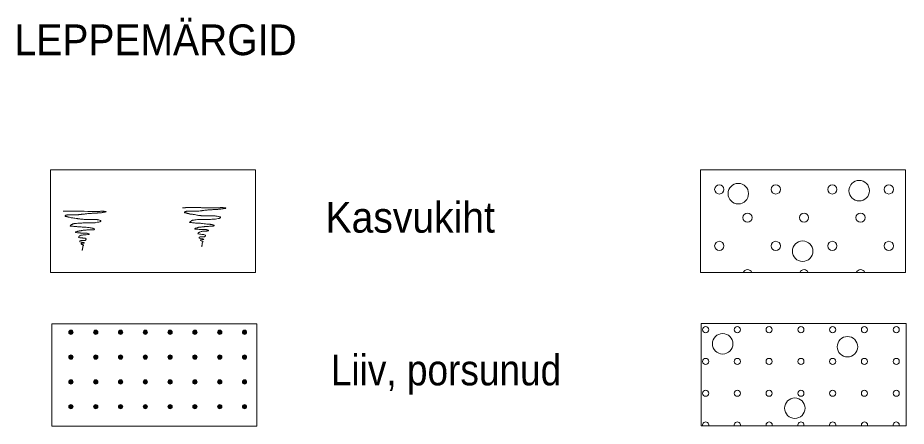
# Model space of a CAD drawing. Extents: x 640104 to 640970, y 6442278 to 6442689.
# Drawn here: x 640605.1 to 640691.8, y 6442439 to 6442478.8 of the extents above; entities that cross this region are included whole.
import ezdxf
from ezdxf.enums import TextEntityAlignment as Align

# ---------------------------------------------------------------- set-up
doc = ezdxf.new("R2010")
doc.units = 0
doc.header["$LTSCALE"] = 1.2
doc.layers.add('50', color=7, linetype='Continuous', lineweight=13)

msp = doc.modelspace()

# ---------------------------------------------------------------- hatches: boundary and pattern name
at = {"layer": '50'}
for points in [[(640610.534, 6442448.158, 1), (640610.114, 6442448.158, 1)], [(640612.954, 6442448.158, 1), (640612.534, 6442448.158, 1)], [(640615.374, 6442448.158, 1), (640614.954, 6442448.158, 1)], [(640617.794, 6442448.158, 1), (640617.374, 6442448.158, 1)], [(640620.214, 6442448.158, 1), (640619.794, 6442448.158, 1)], [(640622.634, 6442448.158, 1), (640622.214, 6442448.158, 1)], [(640625.054, 6442448.158, 1), (640624.634, 6442448.158, 1)], [(640627.474, 6442448.158, 1), (640627.054, 6442448.158, 1)], [(640610.534, 6442445.738, 1), (640610.114, 6442445.738, 1)], [(640612.954, 6442445.738, 1), (640612.534, 6442445.738, 1)], [(640615.374, 6442445.738, 1), (640614.954, 6442445.738, 1)], [(640617.794, 6442445.738, 1), (640617.374, 6442445.738, 1)], [(640620.214, 6442445.738, 1), (640619.794, 6442445.738, 1)], [(640622.634, 6442445.738, 1), (640622.214, 6442445.738, 1)], [(640625.054, 6442445.738, 1), (640624.634, 6442445.738, 1)], [(640627.474, 6442445.738, 1), (640627.054, 6442445.738, 1)], [(640610.534, 6442443.318, 1), (640610.114, 6442443.318, 1)], [(640612.954, 6442443.318, 1), (640612.534, 6442443.318, 1)], [(640615.374, 6442443.318, 1), (640614.954, 6442443.318, 1)], [(640617.794, 6442443.318, 1), (640617.374, 6442443.318, 1)], [(640620.214, 6442443.318, 1), (640619.794, 6442443.318, 1)], [(640622.634, 6442443.318, 1), (640622.214, 6442443.318, 1)], [(640625.054, 6442443.318, 1), (640624.634, 6442443.318, 1)], [(640627.474, 6442443.318, 1), (640627.054, 6442443.318, 1)], [(640610.534, 6442440.898, 1), (640610.114, 6442440.898, 1)], [(640612.954, 6442440.898, 1), (640612.534, 6442440.898, 1)], [(640615.374, 6442440.898, 1), (640614.954, 6442440.898, 1)], [(640617.794, 6442440.898, 1), (640617.374, 6442440.898, 1)], [(640620.214, 6442440.898, 1), (640619.794, 6442440.898, 1)], [(640622.634, 6442440.898, 1), (640622.214, 6442440.898, 1)], [(640625.054, 6442440.898, 1), (640624.634, 6442440.898, 1)], [(640627.474, 6442440.898, 1), (640627.054, 6442440.898, 1)]]:
    msp.add_hatch(color=256, dxfattribs=at).paths.add_polyline_path(points)

# ---------------------------------------------------------------- linework, layer by layer
for points in [[(640608.34, 6442464), (640628.34, 6442464), (640628.34, 6442454), (640608.34, 6442454)], [(640671.77, 6442464), (640691.77, 6442464), (640691.77, 6442454), (640671.77, 6442454)], [(640608.47, 6442448.99), (640628.47, 6442448.99), (640628.47, 6442438.99), (640608.47, 6442438.99)], [(640671.84, 6442449.03), (640691.84, 6442449.03), (640691.84, 6442439.03), (640671.84, 6442439.03)]]:
    msp.add_lwpolyline(points, close=True, dxfattribs=at)
for points in [[(640621.22, 6442460.31), (640621.28, 6442460.31), (640621.38, 6442460.31), (640621.49, 6442460.31), (640621.52, 6442460.33), (640621.62, 6442460.33), (640621.78, 6442460.33), (640622.1, 6442460.33), (640622.28, 6442460.33), (640622.32, 6442460.33), (640622.36, 6442460.33), (640622.43, 6442460.33), (640622.51, 6442460.33), (640622.62, 6442460.33), (640622.7, 6442460.33), (640622.76, 6442460.33), (640622.85, 6442460.33), (640622.92, 6442460.33), (640622.99, 6442460.33), (640623.08, 6442460.31), (640623.12, 6442460.31), (640623.2, 6442460.31), (640623.29, 6442460.31), (640623.63, 6442460.3), (640623.94, 6442460.29), (640624.04, 6442460.29), (640624.1, 6442460.29), (640624.13, 6442460.29), (640624.18, 6442460.29), (640624.25, 6442460.29), (640624.35, 6442460.3), (640624.4, 6442460.3), (640624.43, 6442460.3), (640624.46, 6442460.3), (640624.49, 6442460.3), (640624.56, 6442460.29), (640624.6, 6442460.29), (640624.65, 6442460.29), (640624.74, 6442460.3), (640624.8, 6442460.3), (640624.88, 6442460.31), (640624.91, 6442460.33), (640624.98, 6442460.33), (640625.02, 6442460.34), (640625.07, 6442460.34), (640625.12, 6442460.34), (640625.15, 6442460.33), (640625.19, 6442460.31), (640625.24, 6442460.3), (640625.27, 6442460.3)], [(640625.27, 6442460.3), (640625.32, 6442460.29), (640625.36, 6442460.29), (640625.4, 6442460.29), (640625.43, 6442460.27), (640625.4, 6442460.25), (640625.42, 6442460.27), (640625.38, 6442460.25), (640625.33, 6442460.24), (640625.27, 6442460.23), (640625.24, 6442460.23), (640625.19, 6442460.23), (640625.15, 6442460.22), (640625.12, 6442460.22), (640625.09, 6442460.19), (640625.03, 6442460.19), (640624.96, 6442460.18), (640624.92, 6442460.18), (640624.8, 6442460.17), (640624.76, 6442460.16), (640624.72, 6442460.16), (640624.67, 6442460.15), (640624.62, 6442460.15), (640624.59, 6442460.15), (640624.53, 6442460.13), (640624.49, 6442460.13), (640624.38, 6442460.13), (640624.32, 6442460.13), (640624.25, 6442460.13), (640624.17, 6442460.13), (640624.11, 6442460.12), (640624.06, 6442460.12), (640624, 6442460.11), (640623.94, 6442460.11), (640623.77, 6442460.11), (640623.74, 6442460.11), (640623.7, 6442460.1), (640623.63, 6442460.09), (640623.53, 6442460.07), (640623.45, 6442460.06), (640623.39, 6442460.06), (640623.3, 6442460.05), (640623.24, 6442460.05), (640623.2, 6442460.03), (640623.14, 6442460.03), (640623.11, 6442460.01), (640623.08, 6442460.01), (640623.02, 6442460.01), (640622.97, 6442460), (640622.93, 6442460), (640622.8, 6442459.99), (640622.75, 6442459.99)], [(640609.56, 6442459.97), (640609.62, 6442459.97), (640609.72, 6442459.97), (640609.83, 6442459.97), (640609.86, 6442459.98), (640609.96, 6442459.98), (640610.12, 6442459.98), (640610.44, 6442459.98), (640610.62, 6442459.98), (640610.66, 6442459.98), (640610.7, 6442459.98), (640610.77, 6442459.98), (640610.85, 6442459.98), (640610.96, 6442459.98), (640611.04, 6442459.98), (640611.1, 6442459.98), (640611.19, 6442459.98), (640611.26, 6442459.98), (640611.33, 6442459.98), (640611.42, 6442459.97), (640611.46, 6442459.97), (640611.54, 6442459.97), (640611.63, 6442459.97), (640611.97, 6442459.95), (640612.28, 6442459.94), (640612.38, 6442459.94), (640612.44, 6442459.94), (640612.47, 6442459.94), (640612.52, 6442459.94), (640612.59, 6442459.94), (640612.69, 6442459.95), (640612.74, 6442459.95), (640612.77, 6442459.95), (640612.8, 6442459.95), (640612.83, 6442459.95), (640612.9, 6442459.94), (640612.94, 6442459.94), (640612.99, 6442459.94), (640613.08, 6442459.95), (640613.14, 6442459.95), (640613.22, 6442459.97), (640613.25, 6442459.98), (640613.32, 6442459.98), (640613.36, 6442459.99), (640613.41, 6442459.99), (640613.46, 6442459.99), (640613.49, 6442459.98), (640613.53, 6442459.97), (640613.58, 6442459.95), (640613.61, 6442459.95)], [(640611.09, 6442459.64), (640611.06, 6442459.63), (640611, 6442459.63), (640610.96, 6442459.62), (640610.92, 6442459.62), (640610.89, 6442459.62), (640610.84, 6442459.62), (640610.79, 6442459.62), (640610.74, 6442459.62), (640610.67, 6442459.62), (640610.64, 6442459.62), (640610.58, 6442459.63), (640610.54, 6442459.63), (640610.5, 6442459.63), (640610.47, 6442459.63), (640610.42, 6442459.63), (640610.37, 6442459.63), (640610.3, 6442459.63), (640610.26, 6442459.63), (640610.23, 6442459.63), (640610.17, 6442459.63), (640610.13, 6442459.63), (640610.08, 6442459.63), (640610.05, 6442459.63), (640610, 6442459.63), (640609.95, 6442459.62), (640609.92, 6442459.59), (640609.87, 6442459.59), (640609.83, 6442459.58), (640609.81, 6442459.57), (640609.78, 6442459.56), (640609.76, 6442459.53), (640609.75, 6442459.5), (640609.76, 6442459.46), (640609.86, 6442459.45), (640609.92, 6442459.45), (640609.95, 6442459.43), (640610, 6442459.43), (640610.04, 6442459.41), (640610.06, 6442459.4), (640610.12, 6442459.4), (640610.17, 6442459.39), (640610.2, 6442459.38), (640610.28, 6442459.35), (640610.35, 6442459.34), (640610.42, 6442459.34), (640610.47, 6442459.33), (640610.52, 6442459.32), (640610.6, 6442459.31), (640610.71, 6442459.29)], [(640610.71, 6442459.29), (640610.85, 6442459.27), (640610.95, 6442459.25), (640611.01, 6442459.23), (640611.1, 6442459.22), (640611.2, 6442459.22), (640611.27, 6442459.21), (640611.33, 6442459.21), (640611.38, 6442459.19), (640611.46, 6442459.19), (640611.52, 6442459.19), (640611.61, 6442459.17), (640611.69, 6442459.17), (640611.76, 6442459.17), (640611.86, 6442459.17), (640611.94, 6442459.16), (640612, 6442459.16), (640612.04, 6442459.16), (640612.11, 6442459.16), (640612.18, 6442459.16), (640612.27, 6442459.16), (640612.36, 6442459.16), (640612.45, 6442459.16), (640612.51, 6442459.16), (640612.59, 6442459.16), (640612.63, 6442459.16), (640612.69, 6442459.16), (640612.75, 6442459.16), (640612.81, 6442459.15), (640612.87, 6442459.15), (640612.92, 6442459.14), (640613.05, 6442459.13), (640613.11, 6442459.1), (640613.17, 6442459.08), (640613.22, 6442459.07), (640613.25, 6442459.05), (640613.25, 6442459.02), (640613.24, 6442458.98), (640613.22, 6442458.97), (640613.19, 6442458.96), (640613.17, 6442458.93), (640613.12, 6442458.92), (640613.04, 6442458.9), (640612.89, 6442458.89), (640612.76, 6442458.86), (640612.69, 6442458.85), (640612.59, 6442458.85), (640612.51, 6442458.84), (640612.41, 6442458.84), (640612.28, 6442458.83), (640612.09, 6442458.83), (640611.92, 6442458.83)], [(640613.61, 6442459.95), (640613.66, 6442459.94), (640613.7, 6442459.94), (640613.74, 6442459.94), (640613.77, 6442459.92), (640613.74, 6442459.91), (640613.76, 6442459.92), (640613.72, 6442459.91), (640613.67, 6442459.89), (640613.61, 6442459.88), (640613.58, 6442459.88), (640613.53, 6442459.88), (640613.49, 6442459.87), (640613.46, 6442459.87), (640613.43, 6442459.85), (640613.37, 6442459.85), (640613.3, 6442459.83), (640613.26, 6442459.83), (640613.14, 6442459.82), (640613.1, 6442459.81), (640613.06, 6442459.81), (640613.01, 6442459.8), (640612.96, 6442459.8), (640612.93, 6442459.8), (640612.87, 6442459.79), (640612.83, 6442459.79), (640612.72, 6442459.79), (640612.66, 6442459.79), (640612.59, 6442459.79), (640612.51, 6442459.79), (640612.45, 6442459.77), (640612.4, 6442459.77), (640612.34, 6442459.76), (640612.28, 6442459.76), (640612.11, 6442459.76), (640612.08, 6442459.76), (640612.04, 6442459.75), (640611.97, 6442459.74), (640611.87, 6442459.73), (640611.79, 6442459.71), (640611.73, 6442459.71), (640611.64, 6442459.7), (640611.58, 6442459.7), (640611.54, 6442459.68), (640611.48, 6442459.68), (640611.45, 6442459.67), (640611.42, 6442459.67), (640611.36, 6442459.67), (640611.31, 6442459.65), (640611.27, 6442459.65), (640611.14, 6442459.64), (640611.09, 6442459.64)], [(640622.75, 6442459.99), (640622.72, 6442459.98), (640622.66, 6442459.98), (640622.62, 6442459.97), (640622.58, 6442459.97), (640622.55, 6442459.97), (640622.5, 6442459.97), (640622.45, 6442459.97), (640622.4, 6442459.97), (640622.33, 6442459.97), (640622.3, 6442459.97), (640622.24, 6442459.98), (640622.2, 6442459.98), (640622.16, 6442459.98), (640622.13, 6442459.98), (640622.08, 6442459.98), (640622.03, 6442459.98), (640621.96, 6442459.98), (640621.92, 6442459.98), (640621.89, 6442459.98), (640621.83, 6442459.98), (640621.79, 6442459.98), (640621.74, 6442459.98), (640621.71, 6442459.98), (640621.66, 6442459.98), (640621.61, 6442459.97), (640621.58, 6442459.94), (640621.53, 6442459.94), (640621.49, 6442459.93), (640621.47, 6442459.92), (640621.44, 6442459.91), (640621.42, 6442459.88), (640621.41, 6442459.85), (640621.42, 6442459.81), (640621.52, 6442459.8), (640621.58, 6442459.8), (640621.61, 6442459.77), (640621.66, 6442459.77), (640621.7, 6442459.76), (640621.72, 6442459.75), (640621.78, 6442459.75), (640621.83, 6442459.74), (640621.86, 6442459.73), (640621.94, 6442459.7), (640622.01, 6442459.69), (640622.08, 6442459.69), (640622.13, 6442459.68), (640622.18, 6442459.67), (640622.26, 6442459.65), (640622.37, 6442459.64)], [(640622.37, 6442459.64), (640622.51, 6442459.62), (640622.61, 6442459.59), (640622.67, 6442459.58), (640622.76, 6442459.57), (640622.86, 6442459.57), (640622.93, 6442459.56), (640622.99, 6442459.56), (640623.04, 6442459.53), (640623.12, 6442459.53), (640623.18, 6442459.53), (640623.27, 6442459.52), (640623.35, 6442459.52), (640623.42, 6442459.52), (640623.52, 6442459.52), (640623.6, 6442459.51), (640623.66, 6442459.51), (640623.7, 6442459.51), (640623.77, 6442459.51), (640623.84, 6442459.51), (640623.93, 6442459.51), (640624.02, 6442459.51), (640624.11, 6442459.51), (640624.17, 6442459.51), (640624.25, 6442459.51), (640624.29, 6442459.51), (640624.35, 6442459.51), (640624.41, 6442459.51), (640624.47, 6442459.5), (640624.53, 6442459.5), (640624.58, 6442459.49), (640624.71, 6442459.47), (640624.77, 6442459.45), (640624.83, 6442459.43), (640624.88, 6442459.41), (640624.91, 6442459.4), (640624.91, 6442459.37), (640624.9, 6442459.33), (640624.88, 6442459.32), (640624.85, 6442459.31), (640624.83, 6442459.28), (640624.78, 6442459.27), (640624.7, 6442459.25), (640624.55, 6442459.23), (640624.42, 6442459.21), (640624.35, 6442459.2), (640624.25, 6442459.2), (640624.17, 6442459.19), (640624.07, 6442459.19), (640623.94, 6442459.17), (640623.75, 6442459.17), (640623.58, 6442459.17)], [(640611.92, 6442458.83), (640611.84, 6442458.83), (640611.76, 6442458.83), (640611.68, 6442458.83), (640611.62, 6442458.83), (640611.56, 6442458.83), (640611.48, 6442458.83), (640611.39, 6442458.81), (640611.21, 6442458.81), (640611.13, 6442458.81), (640611.08, 6442458.8), (640611, 6442458.8), (640610.88, 6442458.78), (640610.74, 6442458.78), (640610.7, 6442458.77), (640610.64, 6442458.77), (640610.61, 6442458.75), (640610.58, 6442458.74), (640610.54, 6442458.74), (640610.5, 6442458.73), (640610.47, 6442458.72), (640610.44, 6442458.69), (640610.38, 6442458.66), (640610.35, 6442458.63), (640610.34, 6442458.61), (640610.3, 6442458.6), (640610.29, 6442458.57), (640610.26, 6442458.55), (640610.25, 6442458.53), (640610.28, 6442458.51), (640610.31, 6442458.51), (640610.37, 6442458.51), (640610.42, 6442458.51), (640610.53, 6442458.5), (640610.61, 6442458.49), (640610.71, 6442458.48), (640610.83, 6442458.47), (640610.89, 6442458.47), (640610.95, 6442458.44), (640611.01, 6442458.44), (640611.18, 6442458.44), (640611.31, 6442458.44), (640611.42, 6442458.43), (640611.52, 6442458.42), (640611.67, 6442458.41), (640611.81, 6442458.41), (640611.93, 6442458.37), (640612.02, 6442458.37), (640612.11, 6442458.37), (640612.2, 6442458.36)], [(640612.2, 6442458.36), (640612.24, 6442458.36), (640612.29, 6442458.35), (640612.38, 6442458.32), (640612.45, 6442458.31), (640612.5, 6442458.29), (640612.54, 6442458.27), (640612.6, 6442458.26), (640612.63, 6442458.25), (640612.64, 6442458.2), (640612.62, 6442458.19), (640612.59, 6442458.18), (640612.56, 6442458.17), (640612.44, 6442458.15), (640612.38, 6442458.15), (640612.34, 6442458.15), (640612.27, 6442458.15), (640612.18, 6442458.15), (640612.1, 6442458.14), (640612.05, 6442458.14), (640612, 6442458.14), (640611.87, 6442458.14), (640611.8, 6442458.12), (640611.76, 6442458.12), (640611.7, 6442458.12), (640611.67, 6442458.11), (640611.61, 6442458.11), (640611.52, 6442458.11), (640611.45, 6442458.09), (640611.37, 6442458.08), (640611.31, 6442458.07), (640611.27, 6442458.07), (640611.22, 6442458.07), (640611.19, 6442458.06), (640611.13, 6442458.06), (640611.12, 6442458.03), (640611.06, 6442458.02), (640611.03, 6442458.01), (640611, 6442458.01), (640610.95, 6442458), (640610.89, 6442457.99), (640610.83, 6442457.97), (640610.78, 6442457.95), (640610.76, 6442457.93), (640610.76, 6442457.88), (640610.79, 6442457.88), (640610.86, 6442457.88), (640610.96, 6442457.87), (640611.04, 6442457.87), (640611.09, 6442457.87), (640611.19, 6442457.85), (640611.25, 6442457.85)], [(640623.58, 6442459.17), (640623.5, 6442459.17), (640623.42, 6442459.17), (640623.34, 6442459.17), (640623.28, 6442459.17), (640623.22, 6442459.17), (640623.14, 6442459.17), (640623.05, 6442459.16), (640622.87, 6442459.16), (640622.79, 6442459.16), (640622.74, 6442459.15), (640622.66, 6442459.15), (640622.54, 6442459.13), (640622.4, 6442459.13), (640622.36, 6442459.11), (640622.3, 6442459.11), (640622.27, 6442459.1), (640622.24, 6442459.09), (640622.2, 6442459.09), (640622.16, 6442459.08), (640622.13, 6442459.07), (640622.1, 6442459.04), (640622.04, 6442459.01), (640622.01, 6442458.98), (640622, 6442458.96), (640621.96, 6442458.95), (640621.95, 6442458.92), (640621.92, 6442458.9), (640621.91, 6442458.87), (640621.94, 6442458.86), (640621.97, 6442458.86), (640622.03, 6442458.86), (640622.08, 6442458.86), (640622.19, 6442458.85), (640622.27, 6442458.84), (640622.37, 6442458.83), (640622.49, 6442458.81), (640622.55, 6442458.81), (640622.61, 6442458.79), (640622.67, 6442458.79), (640622.84, 6442458.79), (640622.97, 6442458.79), (640623.08, 6442458.78), (640623.18, 6442458.77), (640623.33, 6442458.75), (640623.47, 6442458.75), (640623.59, 6442458.72), (640623.68, 6442458.72), (640623.77, 6442458.72), (640623.86, 6442458.71)], [(640623.86, 6442458.71), (640623.9, 6442458.71), (640623.95, 6442458.69), (640624.04, 6442458.67), (640624.11, 6442458.66), (640624.16, 6442458.63), (640624.2, 6442458.62), (640624.26, 6442458.61), (640624.29, 6442458.6), (640624.3, 6442458.55), (640624.28, 6442458.54), (640624.25, 6442458.53), (640624.22, 6442458.51), (640624.1, 6442458.5), (640624.04, 6442458.5), (640624, 6442458.5), (640623.93, 6442458.5), (640623.84, 6442458.5), (640623.76, 6442458.49), (640623.71, 6442458.49), (640623.66, 6442458.49), (640623.53, 6442458.49), (640623.46, 6442458.47), (640623.42, 6442458.47), (640623.36, 6442458.47), (640623.33, 6442458.45), (640623.27, 6442458.45), (640623.18, 6442458.45), (640623.11, 6442458.44), (640623.03, 6442458.43), (640622.97, 6442458.42), (640622.93, 6442458.42), (640622.88, 6442458.42), (640622.85, 6442458.41), (640622.79, 6442458.41), (640622.78, 6442458.38), (640622.72, 6442458.37), (640622.69, 6442458.36), (640622.66, 6442458.36), (640622.61, 6442458.35), (640622.55, 6442458.33), (640622.49, 6442458.32), (640622.44, 6442458.3), (640622.42, 6442458.27), (640622.42, 6442458.23), (640622.45, 6442458.23), (640622.52, 6442458.23), (640622.62, 6442458.21), (640622.7, 6442458.21), (640622.75, 6442458.21), (640622.85, 6442458.2), (640622.91, 6442458.2)], [(640611.25, 6442457.85), (640611.27, 6442457.84), (640611.31, 6442457.84), (640611.37, 6442457.84), (640611.44, 6442457.84), (640611.48, 6442457.84), (640611.58, 6442457.83), (640611.67, 6442457.83), (640611.7, 6442457.83), (640611.75, 6442457.83), (640611.79, 6442457.83), (640611.85, 6442457.83), (640611.91, 6442457.82), (640611.96, 6442457.79), (640612, 6442457.78), (640612.05, 6442457.77), (640612.09, 6442457.76), (640612.09, 6442457.71), (640611.97, 6442457.69), (640611.81, 6442457.67), (640611.75, 6442457.67), (640611.64, 6442457.66), (640611.58, 6442457.66), (640611.51, 6442457.66), (640611.44, 6442457.65), (640611.37, 6442457.65), (640611.3, 6442457.63), (640611.21, 6442457.59), (640611.19, 6442457.57), (640611.14, 6442457.54), (640611.12, 6442457.52), (640611.09, 6442457.49), (640611.08, 6442457.46), (640611.06, 6442457.42), (640611.08, 6442457.41), (640611.13, 6442457.4), (640611.2, 6442457.37), (640611.33, 6442457.37), (640611.44, 6442457.36), (640611.5, 6442457.35), (640611.55, 6442457.34), (640611.62, 6442457.34), (640611.7, 6442457.33), (640611.8, 6442457.29), (640611.8, 6442457.24), (640611.79, 6442457.21), (640611.78, 6442457.18), (640611.7, 6442457.12), (640611.67, 6442457.11), (640611.61, 6442457.11), (640611.52, 6442457.11), (640611.44, 6442457.11), (640611.37, 6442457.11), (640611.28, 6442457.11), (640611.2, 6442457.09), (640611.19, 6442457.05), (640611.18, 6442457.03), (640611.19, 6442457), (640611.22, 6442456.99), (640611.34, 6442456.95), (640611.43, 6442456.94), (640611.48, 6442456.93), (640611.54, 6442456.92), (640611.6, 6442456.91), (640611.63, 6442456.88), (640611.61, 6442456.87), (640611.55, 6442456.87), (640611.48, 6442456.86), (640611.38, 6442456.85), (640611.34, 6442456.85), (640611.31, 6442456.83), (640611.31, 6442456.79), (640611.33, 6442456.76), (640611.36, 6442456.75), (640611.39, 6442456.73), (640611.44, 6442456.71), (640611.5, 6442456.7), (640611.55, 6442456.69), (640611.56, 6442456.64), (640611.54, 6442456.62), (640611.52, 6442456.58), (640611.5, 6442456.55), (640611.48, 6442456.52), (640611.48, 6442456.47), (640611.48, 6442456.43), (640611.48, 6442456.39), (640611.46, 6442456.35), (640611.46, 6442456.31), (640611.45, 6442456.28), (640611.44, 6442456.23), (640611.43, 6442456.2), (640611.43, 6442456.15), (640611.43, 6442456.14), (640611.43, 6442456.17)], [(640622.91, 6442458.2), (640622.93, 6442458.19), (640622.97, 6442458.19), (640623.03, 6442458.19), (640623.1, 6442458.19), (640623.14, 6442458.19), (640623.24, 6442458.18), (640623.33, 6442458.18), (640623.36, 6442458.18), (640623.41, 6442458.18), (640623.45, 6442458.18), (640623.51, 6442458.18), (640623.57, 6442458.17), (640623.62, 6442458.14), (640623.66, 6442458.13), (640623.71, 6442458.12), (640623.75, 6442458.11), (640623.75, 6442458.06), (640623.63, 6442458.03), (640623.47, 6442458.02), (640623.41, 6442458.02), (640623.3, 6442458.01), (640623.24, 6442458.01), (640623.17, 6442458.01), (640623.1, 6442458), (640623.03, 6442458), (640622.96, 6442457.97), (640622.87, 6442457.94), (640622.85, 6442457.91), (640622.8, 6442457.89), (640622.78, 6442457.87), (640622.75, 6442457.84), (640622.74, 6442457.81), (640622.72, 6442457.77), (640622.74, 6442457.76), (640622.79, 6442457.75), (640622.86, 6442457.72), (640622.99, 6442457.72), (640623.1, 6442457.71), (640623.16, 6442457.7), (640623.21, 6442457.69), (640623.28, 6442457.69), (640623.36, 6442457.67), (640623.46, 6442457.64), (640623.46, 6442457.59), (640623.45, 6442457.55), (640623.44, 6442457.53), (640623.36, 6442457.47), (640623.33, 6442457.46), (640623.27, 6442457.46), (640623.18, 6442457.46), (640623.1, 6442457.46), (640623.03, 6442457.46), (640622.94, 6442457.46), (640622.86, 6442457.43), (640622.85, 6442457.4), (640622.84, 6442457.37), (640622.85, 6442457.35), (640622.88, 6442457.34), (640623, 6442457.3), (640623.09, 6442457.29), (640623.14, 6442457.28), (640623.2, 6442457.27), (640623.26, 6442457.25), (640623.29, 6442457.23), (640623.27, 6442457.22), (640623.21, 6442457.22), (640623.14, 6442457.21), (640623.04, 6442457.19), (640623, 6442457.19), (640622.97, 6442457.18), (640622.97, 6442457.13), (640622.99, 6442457.11), (640623.02, 6442457.1), (640623.05, 6442457.07), (640623.1, 6442457.06), (640623.16, 6442457.05), (640623.21, 6442457.04), (640623.22, 6442456.99), (640623.2, 6442456.97), (640623.18, 6442456.93), (640623.16, 6442456.89), (640623.14, 6442456.87), (640623.14, 6442456.82), (640623.14, 6442456.77), (640623.14, 6442456.74), (640623.12, 6442456.7), (640623.12, 6442456.65), (640623.11, 6442456.63), (640623.1, 6442456.58), (640623.09, 6442456.55), (640623.09, 6442456.5), (640623.09, 6442456.49), (640623.09, 6442456.52)]]:
    msp.add_lwpolyline(points, dxfattribs=at)
for centre, radius in [((640687.25, 6442461.974), 1), ((640673.595, 6442462.1), 0.45), ((640675.45, 6442461.688), 1), ((640679.111, 6442462.1), 0.45), ((640684.626, 6442462.1), 0.45), ((640690.141, 6442462.1), 0.45), ((640676.353, 6442459.343), 0.45), ((640681.868, 6442459.343), 0.45), ((640687.384, 6442459.343), 0.45), ((640673.595, 6442456.585), 0.45), ((640679.111, 6442456.585), 0.45), ((640681.731, 6442456.073), 1), ((640684.626, 6442456.585), 0.45), ((640690.141, 6442456.585), 0.45), ((640610.324, 6442448.158), 0.21), ((640612.744, 6442448.158), 0.21), ((640615.164, 6442448.158), 0.21), ((640617.584, 6442448.158), 0.21), ((640620.004, 6442448.158), 0.21), ((640622.424, 6442448.158), 0.21), ((640624.844, 6442448.158), 0.21), ((640627.264, 6442448.158), 0.21), ((640672.263, 6442448.408), 0.3), ((640673.927, 6442447.033), 1), ((640675.363, 6442448.408), 0.3), ((640678.463, 6442448.408), 0.3), ((640681.563, 6442448.408), 0.3), ((640684.663, 6442448.408), 0.3), ((640687.763, 6442448.408), 0.3), ((640690.863, 6442448.408), 0.3), ((640686.108, 6442446.747), 1), ((640610.324, 6442445.738), 0.21), ((640612.744, 6442445.738), 0.21), ((640615.164, 6442445.738), 0.21), ((640617.584, 6442445.738), 0.21), ((640620.004, 6442445.738), 0.21), ((640622.424, 6442445.738), 0.21), ((640624.844, 6442445.738), 0.21), ((640627.264, 6442445.738), 0.21), ((640672.263, 6442445.308), 0.3), ((640675.363, 6442445.308), 0.3), ((640678.463, 6442445.308), 0.3), ((640681.563, 6442445.308), 0.3), ((640684.663, 6442445.308), 0.3), ((640687.763, 6442445.308), 0.3), ((640690.863, 6442445.308), 0.3), ((640610.324, 6442443.318), 0.21), ((640612.744, 6442443.318), 0.21), ((640615.164, 6442443.318), 0.21), ((640617.584, 6442443.318), 0.21), ((640620.004, 6442443.318), 0.21), ((640622.424, 6442443.318), 0.21), ((640624.844, 6442443.318), 0.21), ((640627.264, 6442443.318), 0.21), ((640672.263, 6442442.208), 0.3), ((640675.363, 6442442.208), 0.3), ((640678.463, 6442442.208), 0.3), ((640681.563, 6442442.208), 0.3), ((640684.663, 6442442.208), 0.3), ((640687.763, 6442442.208), 0.3), ((640690.863, 6442442.208), 0.3), ((640610.324, 6442440.898), 0.21), ((640612.744, 6442440.898), 0.21), ((640615.164, 6442440.898), 0.21), ((640617.584, 6442440.898), 0.21), ((640620.004, 6442440.898), 0.21), ((640622.424, 6442440.898), 0.21), ((640624.844, 6442440.898), 0.21), ((640627.264, 6442440.898), 0.21), ((640680.969, 6442440.752), 1)]:
    msp.add_circle(centre, radius, dxfattribs=at)
for centre, radius, start, end in [((640676.353, 6442453.827), 0.45, 23.21772, 156.78228), ((640681.868, 6442453.827), 0.45, 23.21772, 156.78228), ((640687.384, 6442453.827), 0.45, 23.21772, 156.78228), ((640672.263, 6442439.108), 0.3, 345.47373, 194.52627), ((640675.363, 6442439.108), 0.3, 345.47373, 194.52627), ((640678.463, 6442439.108), 0.3, 345.47373, 194.52627), ((640681.563, 6442439.108), 0.3, 345.47373, 194.52627), ((640684.663, 6442439.108), 0.3, 345.47373, 194.52627), ((640687.763, 6442439.108), 0.3, 345.47373, 194.52627), ((640690.863, 6442439.108), 0.3, 345.47373, 194.52627)]:
    msp.add_arc(centre, radius, start, end, dxfattribs=at)

# ---------------------------------------------------------------- texts
for s, width, p in [('LEPPEMÄRGID', 0.95, (640618.59, 6442475.2)), ('Kasvukiht', 0.95, (640643.435, 6442457.88)), ('Liiv, porsunud', 0.9, (640646.93, 6442442.98))]:
    msp.add_text(s, height=3, dxfattribs=dict(at, width=width)).set_placement(p, align=Align.CENTER)

doc.saveas('drawing.dxf')
